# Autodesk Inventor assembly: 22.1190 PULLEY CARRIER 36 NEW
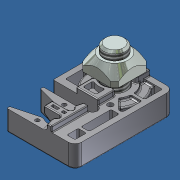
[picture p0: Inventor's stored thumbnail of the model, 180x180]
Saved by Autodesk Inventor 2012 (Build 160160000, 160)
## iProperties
Created: 2017-03
Part Number: 22.1190 PULLEY CARRIER 36 NEW
Document SubType Name: Assembly
Designer: Admin
Mass: 18.6985 g
Surface Area: 60.4636 cm^2
Volume: 6.34349 cm^3
Density: 2.94767 g/cm^3
Author: Admin
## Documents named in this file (4)
- Y:\INVENTOR LIBRARIES\PARTS LIBRARY\BELT AND ROLLER CONVEYORS\22.1190 PULLEY CARRIER 36 NEW.iam
- Y:\INVENTOR LIBRARIES\PARTS LIBRARY\FASTENING ELEMENTS\SCREWS CAP\21.1200 M8X16.ipt
- Y:\INVENTOR LIBRARIES\PARTS LIBRARY\FASTENING ELEMENTS\NUTS\21.1351 M8 SQUARE NUT.ipt
- Y:\INVENTOR LIBRARIES\PARTS LIBRARY\BELT AND ROLLER CONVEYORS\SUBCOMPONENTS\22.1191_1 PULLY CARRIER PLASTIC BODY.ipt
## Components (3 placed, 3 different names)
1. 22.1191_1 PULLY CARRIER PLASTIC BODY:1 — Flush:4, Mate:4, Mate:5, Insert:2, Mate:7, Angle:4
2. 21.1200 M8 x 16:2 — Insert:2, Mate:6
3. 21.1351 M8 SQUARE NUT:2 — Mate:6, Mate:7, Angle:4
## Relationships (7: Mate 4, Flush 1, Insert 1, Angle 1)
- Flush:4: 22.1191_1 PULLY CARRIER PLASTIC BODY:1
- Mate:4: 22.1191_1 PULLY CARRIER PLASTIC BODY:1
- Mate:5: 22.1191_1 PULLY CARRIER PLASTIC BODY:1
- Insert:2: 22.1191_1 PULLY CARRIER PLASTIC BODY:1 ↔ 21.1200 M8 x 16:2
- Mate:6: 21.1200 M8 x 16:2 ↔ 21.1351 M8 SQUARE NUT:2
- Mate:7: 22.1191_1 PULLY CARRIER PLASTIC BODY:1 ↔ 21.1351 M8 SQUARE NUT:2
- Angle:4: 22.1191_1 PULLY CARRIER PLASTIC BODY:1 ↔ 21.1351 M8 SQUARE NUT:2
